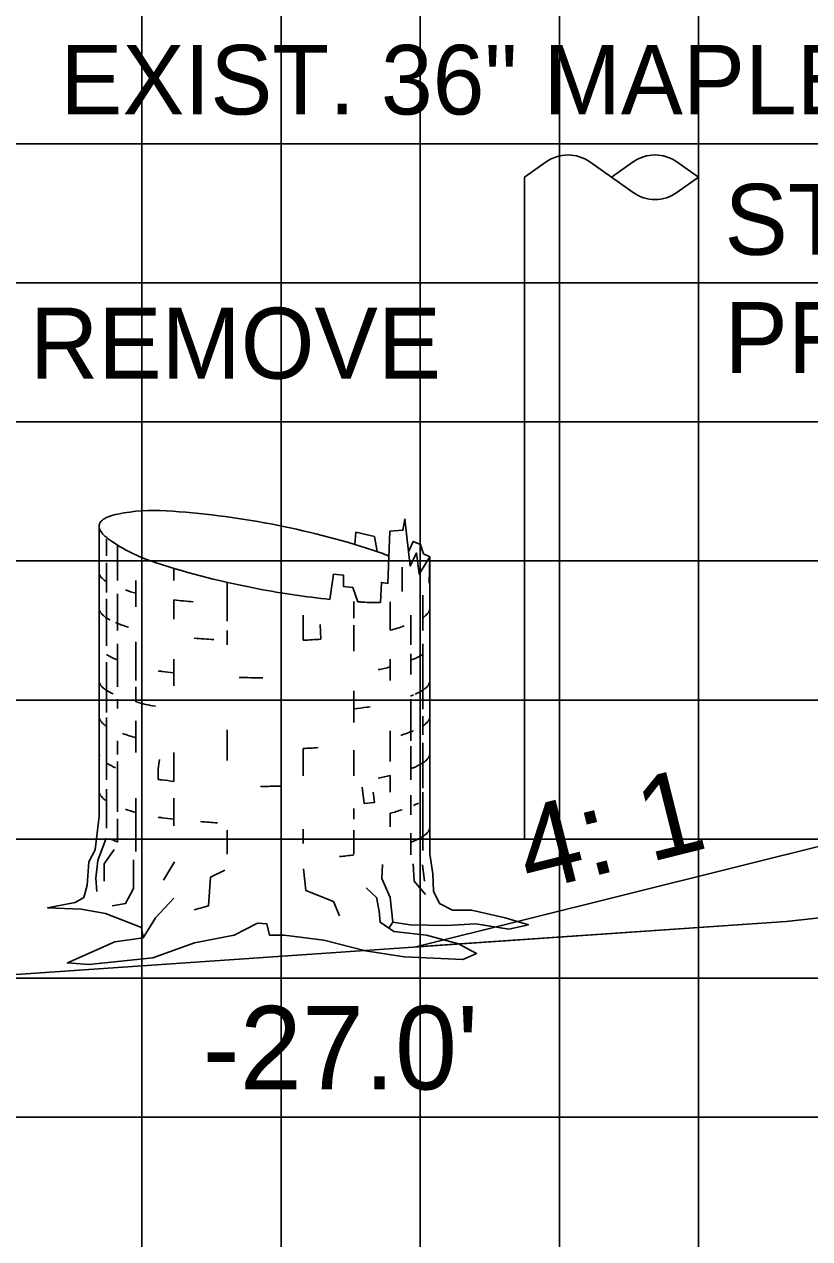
# Model space of a CAD drawing. Extents: x 854676 to 854846, y 366268 to 366378.
# Drawn here: x 854729.26 to 854734.91, y 366362.44 to 366371.17 of the extents above; entities that cross this region are included whole.
import ezdxf

# ---------------------------------------------------------------- set-up
doc = ezdxf.new("R2010")
doc.units = 0
for name, color, linetype in [('ANNOTATION', 7, 'Continuous'), ('D_Roadway_FinishedGrade', 7, 'Continuous'), ('D_Text_Monospaced', 7, 'Continuous'), ('D_Text_Standard', 7, 'Continuous'), ('D_Utilities_Pole_Joint', 7, 'Continuous'), ('D_Utilities_Text', 7, 'Continuous'), ('JUNK FILL', 7, 'Continuous'), ('MAJOR', 7, 'Continuous'), ('MINOR', 7, 'Continuous'), ('S_Roadway_Centerline', 7, 'Continuous'), ('S_Trees_Decid_Pay', 7, 'Continuous')]:
    doc.layers.add(name, color=color, linetype=linetype)

msp = doc.modelspace()

# ---------------------------------------------------------------- linework, layer by layer
at = {"layer": 'D_Roadway_FinishedGrade'}
msp.add_line((854732.075, 366364.534), (854735.1014, 366365.2906), dxfattribs=at)
at = {"layer": 'D_Utilities_Pole_Joint'}
for p, q in [((854732.8563, 366370.0684), (854733.0125, 366370.1787)), ((854733.3248, 366370.1787), (854733.481, 366370.0684)), ((854733.6372, 366370.1787), (854733.481, 366370.0684)), ((854734.1063, 366370.0684), (854733.9502, 366370.1787)), ((854732.8563, 366365.3106), (854732.8563, 366370.0684)), ((854733.481, 366370.0684), (854733.6372, 366369.9576)), ((854733.9502, 366369.9576), (854734.1063, 366370.0684)), ((854734.1063, 366365.3106), (854734.1063, 366370.0684))]:
    msp.add_line(p, q, dxfattribs=at)
for centre, start, end in [((854733.1686, 366369.9578), 90, 125.26439), ((854733.1686, 366369.9578), 54.73561, 90), ((854733.7936, 366369.9578), 90, 125.26439), ((854733.7936, 366369.9578), 54.73561, 90), ((854733.7936, 366370.1788), 234.73561, 270), ((854733.7936, 366370.1788), 270, 305.26439)]:
    msp.add_arc(centre, 0.2706, start, end, dxfattribs=at)
at = {"layer": 'JUNK FILL'}
msp.add_lwpolyline([(854735.1063, 366364.7577), (854735.1063, 366365.2906), (854735.1014, 366365.2906), (854732.075, 366364.534), (854734.737, 366364.7173)], close=True, dxfattribs=at)
at = {"layer": 'MAJOR'}
for p, q in [((854734.1063, 366353.3091), (854734.1063, 366373.3091)), ((854689.1063, 366368.3091), (854829.1063, 366368.3091)), ((854689.1063, 366363.3091), (854829.1063, 366363.3091))]:
    msp.add_line(p, q, dxfattribs=at)
at = {"layer": 'MINOR'}
for p, q in [((854730.1063, 366353.3091), (854730.1063, 366373.3091)), ((854731.1063, 366353.3091), (854731.1063, 366373.3091)), ((854732.1063, 366353.3091), (854732.1063, 366373.3091)), ((854733.1063, 366353.3091), (854733.1063, 366373.3091)), ((854689.1063, 366370.3091), (854829.1063, 366370.3091)), ((854689.1063, 366369.3091), (854829.1063, 366369.3091)), ((854689.1063, 366367.3091), (854829.1063, 366367.3091)), ((854689.1063, 366366.3091), (854829.1063, 366366.3091)), ((854689.1063, 366365.3091), (854829.1063, 366365.3091)), ((854689.1063, 366364.3091), (854829.1063, 366364.3091))]:
    msp.add_line(p, q, dxfattribs=at)
at = {"layer": 'S_Roadway_Centerline'}
msp.add_lwpolyline([(854696.3673, 366363.2907), (854702.4938, 366363.7061), (854707.8783, 366363.8716), (854728.5765, 366364.293), (854734.737, 366364.7173), (854737.8845, 366365.0609), (854738.3684, 366365.0916), (854742.1275, 366364.878), (854742.2093, 366364.875), (854748.431, 366365.0464), (854748.4566, 366365.0475), (854748.494, 366365.05), (854750.6841, 366365.0857), (854759.8334, 366365.231), (854760.071, 366365.2256), (854771.0875, 366364.9954)], dxfattribs=at)
at = {"layer": 'S_Trees_Decid_Pay'}
for p, q in [((854729.8517, 366367.4677), (854729.8517, 366367.347)), ((854729.9318, 366367.4231), (854729.9318, 366367.1698)), ((854729.8517, 366367.2951), (854729.8517, 366367.0812)), ((854730.3366, 366367.2564), (854730.3366, 366367.1698)), ((854731.9764, 366367.2643), (854731.9764, 366367.0898)), ((854730.0643, 366367.1698), (854730.0643, 366366.9782)), ((854730.7198, 366367.1554), (854730.7198, 366366.8752)), ((854729.9318, 366367.0734), (854729.9318, 366366.8096)), ((854732.126, 366367.0642), (854732.126, 366366.8096)), ((854729.8517, 366367.036), (854729.8517, 366366.698)), ((854730.3366, 366367.0287), (854730.3366, 366366.8896)), ((854731.6306, 366367.0176), (854731.6306, 366366.8982)), ((854731.8917, 366367.0156), (854731.8917, 366366.8109)), ((854731.2657, 366366.9185), (854731.2657, 366366.7387)), ((854732.04, 366366.9185), (854732.04, 366366.7066)), ((854730.7198, 366366.8096), (854730.7198, 366366.7066)), ((854731.3924, 366366.7459), (854731.3871, 366366.8529)), ((854731.6306, 366366.8463), (854731.6306, 366366.6613)), ((854729.9318, 366366.7125), (854729.9318, 366366.4041)), ((854730.0643, 366366.7269), (854730.0643, 366366.4493)), ((854732.126, 366366.7125), (854732.126, 366366.2433)), ((854732.04, 366366.6409), (854732.04, 366366.4927)), ((854729.8517, 366366.5812), (854729.8517, 366366.2203)), ((854730.3366, 366366.6035), (854730.3366, 366366.4119)), ((854731.8917, 366366.6035), (854731.8917, 366366.4493)), ((854730.0643, 366366.4041), (854730.0643, 366366.2951)), ((854731.6306, 366366.3752), (854731.6306, 366366.1469)), ((854729.9318, 366366.3155), (854729.9318, 366366.2492)), ((854732.04, 366366.3155), (854732.04, 366366.015)), ((854729.8517, 366366.1836), (854729.8517, 366365.7348)), ((854732.126, 366366.1921), (854732.126, 366366.0583)), ((854730.0643, 366366.1606), (854730.0643, 366365.9323)), ((854730.7198, 366366.095), (854730.7198, 366365.8745)), ((854729.9318, 366366.015), (854729.9318, 366365.9179)), ((854731.8917, 366366.0865), (854731.8917, 366365.8667)), ((854730.3366, 366365.9323), (854730.3366, 366365.7243)), ((854731.2657, 366365.9605), (854731.2657, 366365.7637)), ((854731.6306, 366365.9487), (854731.6306, 366365.7637)), ((854732.04, 366365.9776), (854732.04, 366365.7348)), ((854732.126, 366366.0005), (854732.126, 366365.6751)), ((854729.9318, 366365.8667), (854729.9318, 366365.5064)), ((854731.8917, 366365.7669), (854731.8917, 366365.6462)), ((854729.8517, 366365.6692), (854729.8517, 366365.387)), ((854730.0643, 366365.6029), (854730.0643, 366365.2197)), ((854730.3366, 366365.6029), (854730.3366, 366365.4034)), ((854732.04, 366365.6239), (854732.04, 366365.4835)), ((854732.126, 366365.6462), (854732.126, 366365.2263)), ((854731.6306, 366365.5287), (854731.6306, 366365.452)), ((854731.8917, 366365.4953), (854731.8917, 366365.3969)), ((854729.9318, 366365.4546), (854729.9318, 366365.2879)), ((854730.7198, 366365.3745), (854730.7198, 366365.2013)), ((854731.2657, 366365.3805), (854731.2657, 366365.2774)), ((854731.6306, 366365.3745), (854731.6306, 366365.2013)), ((854732.04, 366365.3516), (854732.04, 366365.1954)), ((854730.3412, 366365.1462), (854730.2611, 366365.0143)), ((854732.1227, 366365.1232), (854732.1371, 366365.0058))]:
    msp.add_line(p, q, dxfattribs=at)
for points in [[(854731.8202, 366367.011), (854731.8281, 366367.1554), (854731.8734, 366367.1475), (854731.8878, 366367.5222), (854731.9823, 366367.5301), (854731.9967, 366367.6101), (854732.0341, 366367.2728), (854732.0794, 366367.3673), (854732.0997, 366367.2131), (854732.1765, 366367.3385), (854732.1706, 366367.1488)], [(854732.1765, 366367.3385), (854732.1765, 366365.2013), (854732.1968, 366365.0596), (854732.2027, 366364.9336), (854732.2461, 366364.847), (854732.3386, 366364.7978), (854732.4744, 366364.7978), (854732.7178, 366364.742), (854732.8845, 366364.6928), (854732.7421, 366364.6619), (854732.5052, 366364.6993), (854732.2953, 366364.6869), (854732.0341, 366364.6928), (854731.9101, 366364.7112), (854731.8799, 366364.6685), (854731.8176, 366364.7112), (854731.9167, 366364.6436), (854732.1516, 366364.6186), (854732.3819, 366364.557), (854732.5118, 366364.4868), (854732.4127, 366364.4434), (854731.9908, 366364.4625), (854731.7126, 366364.5058), (854731.414, 366364.5819), (854731.1279, 366364.6186), (854731.023, 366364.6186), (854731.0046, 366364.6993), (854730.9363, 366364.7053), (854730.7697, 366364.6186), (854730.4836, 366364.5629), (854730.185, 366364.4559), (854729.7257, 366364.4067), (854729.5715, 366364.4192), (854729.9134, 366364.5694), (854730.1168, 366364.6003), (854730.105, 366364.6744), (854729.8451, 366364.7735), (854729.6699, 366364.8043), (854729.4291, 366364.8161), (854729.6273, 366364.8535), (854729.689, 366364.8903), (854729.7132, 366364.9769), (854729.7257, 366365.1462), (854729.771, 366365.2322), (854729.7992, 366365.473), (854729.7992, 366367.5589)], [(854731.7979, 366367.3772), (854731.7769, 366367.4848), (854731.645, 366367.5156), (854731.6378, 366367.4277)], [(854732.1765, 366367.3385), (854732.1306, 366367.3614), (854732.1083, 366367.427), (854732.0564, 366367.45), (854732.023, 366367.3752)], [(854731.6588, 366367.0156), (854731.622, 366367.1186), (854731.5564, 366367.1245), (854731.5564, 366367.2066), (854731.4823, 366367.2131), (854731.4573, 366367.0327)], [(854730.2231, 366365.7381), (854730.2244, 366365.8148), (854730.2323, 366365.8811)], [(854731.7684, 366365.6462), (854731.7769, 366365.5721), (854731.7027, 366365.5661), (854731.6883, 366365.6829)], [(854729.8497, 366365.3148), (854729.7894, 366365.1541), (854729.7756, 366365.0287), (854729.7835, 366364.9316)], [(854729.9068, 366365.2341), (854729.8353, 366365.1311), (854729.8353, 366365.0058)], [(854730.0472, 366365.16), (854730.0472, 366364.9546), (854729.9895, 366364.845), (854729.8924, 366364.8286)], [(854732.0564, 366365.1311), (854732.063, 366365.0058), (854732.145, 366364.9113)], [(854730.7021, 366365.0858), (854730.5991, 366365.0347), (854730.5846, 366364.8286), (854730.4816, 366364.7997)], [(854731.2677, 366365.0944), (854731.2848, 366364.9402), (854731.4823, 366364.8595), (854731.5276, 366364.7564)], [(854731.9101, 366364.7112), (854731.8917, 366364.8903), (854731.83, 366365.0268), (854731.8366, 366365.1272)], [(854731.7192, 366364.9585), (854731.7933, 366364.8903), (854731.8117, 366364.7919), (854731.8176, 366364.7112)], [(854730.1168, 366364.6003), (854730.2034, 366364.742), (854730.3353, 366364.8844)]]:
    msp.add_lwpolyline(points, dxfattribs=at)
for centre, radius, start, end in [((854730.1975, 366366.3737), 1.2994, 86.30559, 101.72212), ((854729.8865, 366361.5574), 6.1257, 79.22212, 86.30559), ((854729.8458, 366367.5591), 0.0467, 157.53998, 169.22212), ((854729.8529, 366367.5561), 0.0544, 146.72212, 157.53998), ((854729.8613, 366367.5506), 0.0645, 134.0453, 146.72212), ((854729.8911, 366367.5199), 0.1073, 124.22212, 134.0453), ((854729.9229, 366367.473), 0.164, 110.01568, 124.22212), ((854730.0309, 366367.1765), 0.4795, 101.72212, 110.01568), ((854729.8865, 366361.5574), 6.1257, 72.13866, 79.22212), ((854729.8458, 366367.5591), 0.0467, 169.22212, 180.90426), ((854729.8535, 366367.5592), 0.0544, 180.90426, 191.72212), ((854729.8634, 366367.5613), 0.0645, 191.72212, 204.39894), ((854729.9023, 366367.5789), 0.1073, 204.39894, 214.22212), ((854729.9492, 366367.6108), 0.164, 214.22212, 228.42856), ((854730.1586, 366367.8469), 0.4795, 228.42856, 236.72212), ((854730.6084, 366368.5323), 1.2994, 236.72212, 252.13866), ((854731.3668, 366366.1511), 1.2994, 66.6931, 72.13866), ((854732.0887, 366373.126), 6.1257, 252.13866, 259.22212), ((854729.8533, 366367.2325), 0.0554, 191.68146, 202.5), ((854729.8628, 366367.2364), 0.0657, 202.5, 215.17372), ((854729.8983, 366367.2614), 0.1091, 215.17372, 225), ((854729.9389, 366367.302), 0.1665, 225, 238.32996), ((854730.4107, 366368.3213), 1.292, 250.90844, 254.43487), ((854732.0887, 366373.126), 6.1257, 259.22212, 264.08527), ((854730.9866, 366372.9092), 5.916, 263.69125, 265.04855), ((854732.0887, 366373.126), 6.1257, 265.97538, 266.30559), ((854731.7777, 366368.3097), 1.2994, 266.30559, 271.87106), ((854732.1286, 366366.9701), 0.0476, 348.31854, 0), ((854729.8543, 366366.9717), 0.0554, 191.68146, 202.5), ((854729.8638, 366366.9756), 0.0657, 202.5, 215.17372), ((854729.8993, 366367.0006), 0.1091, 215.17372, 225), ((854729.9399, 366367.0412), 0.1665, 225, 239.19244), ((854730.1026, 366367.3141), 0.4843, 239.19244, 242.58383), ((854732.0354, 366367.0412), 0.1665, 300.80756, 315), ((854732.076, 366367.0006), 0.1091, 315, 324.82628), ((854732.1115, 366366.9756), 0.0657, 324.82628, 337.5), ((854732.1209, 366366.9717), 0.0554, 337.5, 348.31854), ((854730.4117, 366368.0604), 1.292, 247.5, 251.91706), ((854731.5635, 366368.0604), 1.292, 284.71442, 289.38813), ((854730.9876, 366372.6484), 5.916, 265.10761, 266.46179), ((854730.9876, 366372.6484), 5.916, 272.69566, 273.92236), ((854729.9399, 366366.7776), 0.1665, 238.3999, 239.19244), ((854730.1026, 366367.0506), 0.4843, 239.19244, 247.5), ((854731.8727, 366367.0506), 0.4843, 292.5, 300.80756), ((854732.0354, 366366.7776), 0.1665, 300.80756, 302.96221), ((854730.4117, 366367.7969), 1.292, 247.5, 248.1929), ((854731.5635, 366367.7969), 1.292, 280.73677, 284.71442), ((854731.5635, 366367.7969), 1.292, 291.64627, 292.5), ((854729.8543, 366366.4508), 0.0554, 191.68146, 202.5), ((854730.4117, 366367.7969), 1.292, 261.63381, 262.84537), ((854730.9876, 366372.3848), 5.916, 262.84537, 263.68165), ((854730.9876, 366372.3848), 5.916, 268.22917, 269.8838), ((854732.1209, 366366.4508), 0.0554, 337.5, 348.31854), ((854732.1286, 366366.4492), 0.0476, 348.31854, 0), ((854729.8638, 366366.4547), 0.0657, 202.5, 215.17372), ((854729.8993, 366366.4797), 0.1091, 215.17372, 225), ((854729.9399, 366366.5203), 0.1665, 225, 239.19244), ((854730.1026, 366366.7932), 0.4843, 239.19244, 245.36279), ((854731.8727, 366366.7932), 0.4843, 294.22755, 300.80756), ((854732.0354, 366366.5203), 0.1665, 300.80756, 315), ((854732.076, 366366.4797), 0.1091, 315, 324.82628), ((854732.1115, 366366.4547), 0.0657, 324.82628, 337.5), ((854730.4117, 366367.5395), 1.292, 254.3895, 260.74346), ((854731.5635, 366367.5395), 1.292, 291.51583, 292.5), ((854729.8543, 366366.1934), 0.0554, 191.68146, 202.5), ((854730.9876, 366372.1274), 5.916, 276.2405, 277.15463), ((854731.5635, 366367.5395), 1.292, 277.15462, 278.12742), ((854732.1209, 366366.1934), 0.0554, 337.5, 348.31854), ((854732.1286, 366366.1918), 0.0476, 348.31854, 0), ((854729.8638, 366366.1973), 0.0657, 202.5, 215.17372), ((854729.8993, 366366.2223), 0.1091, 215.17372, 225), ((854729.9399, 366366.2629), 0.1665, 225, 237.93061), ((854732.0354, 366366.2629), 0.1665, 300.80756, 315), ((854732.076, 366366.2223), 0.1091, 315, 324.82628), ((854732.1115, 366366.1973), 0.0657, 324.82628, 337.5), ((854730.4117, 366367.2821), 1.292, 249.89985, 254.38951), ((854731.5635, 366367.2821), 1.292, 288.20102, 292.5), ((854729.8543, 366365.9278), 0.0554, 191.68146, 202.5), ((854730.9876, 366371.8701), 5.916, 272.69566, 273.72789), ((854732.1209, 366365.9278), 0.0554, 337.5, 348.31854), ((854732.1286, 366365.9262), 0.0476, 348.31854, 0), ((854729.9399, 366365.9973), 0.1665, 237.93061, 239.19244), ((854730.1026, 366366.2702), 0.4843, 239.19244, 247.5), ((854731.8727, 366366.2702), 0.4843, 292.5, 300.80756), ((854732.0354, 366365.9973), 0.1665, 300.80756, 315), ((854732.076, 366365.9567), 0.1091, 315, 324.82628), ((854732.1115, 366365.9317), 0.0657, 324.82628, 337.5), ((854731.5635, 366367.0165), 1.292, 280.75372, 284.71442), ((854731.5635, 366367.0165), 1.292, 291.64627, 292.5), ((854730.4117, 366367.0165), 1.292, 261.62048, 262.84537), ((854730.9876, 366371.6045), 5.916, 262.84537, 263.68165), ((854730.9876, 366371.6045), 5.916, 269.72432, 270), ((854730.9876, 366371.6045), 5.916, 270, 271.07935), ((854729.8543, 366365.656), 0.0554, 191.68146, 202.5), ((854729.8638, 366365.6599), 0.0657, 202.5, 215.17372), ((854729.8993, 366365.6849), 0.1091, 215.17372, 225), ((854729.9399, 366365.7255), 0.1665, 225, 237.93061), ((854731.8727, 366365.9985), 0.4843, 292.5, 297.26599), ((854730.4117, 366366.7448), 1.292, 250.84664, 254.38951), ((854731.5635, 366366.7448), 1.292, 284.71442, 288.63358), ((854730.4117, 366366.7448), 1.292, 261.63381, 262.84537), ((854730.9876, 366371.3327), 5.916, 262.84537, 263.68165), ((854730.9876, 366371.3327), 5.916, 265.53898, 266.73634), ((854732.1286, 366365.397), 0.0476, 348.31854, 0), ((854730.1026, 366365.7411), 0.4843, 243.45008, 247.5), ((854731.8727, 366365.7411), 0.4843, 292.5, 300.80756), ((854732.0354, 366365.4681), 0.1665, 300.80756, 315), ((854732.076, 366365.4276), 0.1091, 315, 324.82628), ((854732.1115, 366365.4026), 0.0657, 324.82628, 337.5), ((854732.1209, 366365.3986), 0.0554, 337.5, 348.31854), ((854730.4026, 366366.4911), 1.292, 247.9396, 248.63037), ((854731.5635, 366366.4874), 1.292, 291.64627, 292.5), ((854730.9876, 366371.0753), 5.916, 275.23445, 276.21686)]:
    msp.add_arc(centre, radius, start, end, dxfattribs=at)

# ---------------------------------------------------------------- texts
at = {"layer": 'ANNOTATION'}
msp.add_text('4: 1', height=0.6, rotation=14.03624, dxfattribs=at).set_placement((854732.8895, 366364.9259))
at = {"layer": 'D_Text_Monospaced'}
msp.add_text('EXIST. 36" MAPLE', height=0.49998, dxfattribs=at).set_placement((854729.5208, 366370.5197))
at = {"layer": 'D_Text_Standard'}
msp.add_text("-27.0'", height=0.6, dxfattribs=at).set_placement((854730.5428, 366363.5091))
at = {"layer": 'D_Utilities_Text'}
for s, p in [("STA. 278+97, 25' LT.", (854734.2927, 366369.5104)), ('PROP. POLE', (854734.2927, 366368.6604)), ('REMOVE', (854729.301, 366368.6203))]:
    msp.add_text(s, height=0.51, dxfattribs=at).set_placement(p)

doc.saveas('drawing.dxf')
